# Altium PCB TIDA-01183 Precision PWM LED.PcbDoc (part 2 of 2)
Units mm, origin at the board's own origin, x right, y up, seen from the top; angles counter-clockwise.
Board outline 88 x 70 mm, 2 copper layers (Top Layer, Bottom Layer), stack 1.575 mm thick; 108 components, 41 nets, 240 pads, 138 vias.
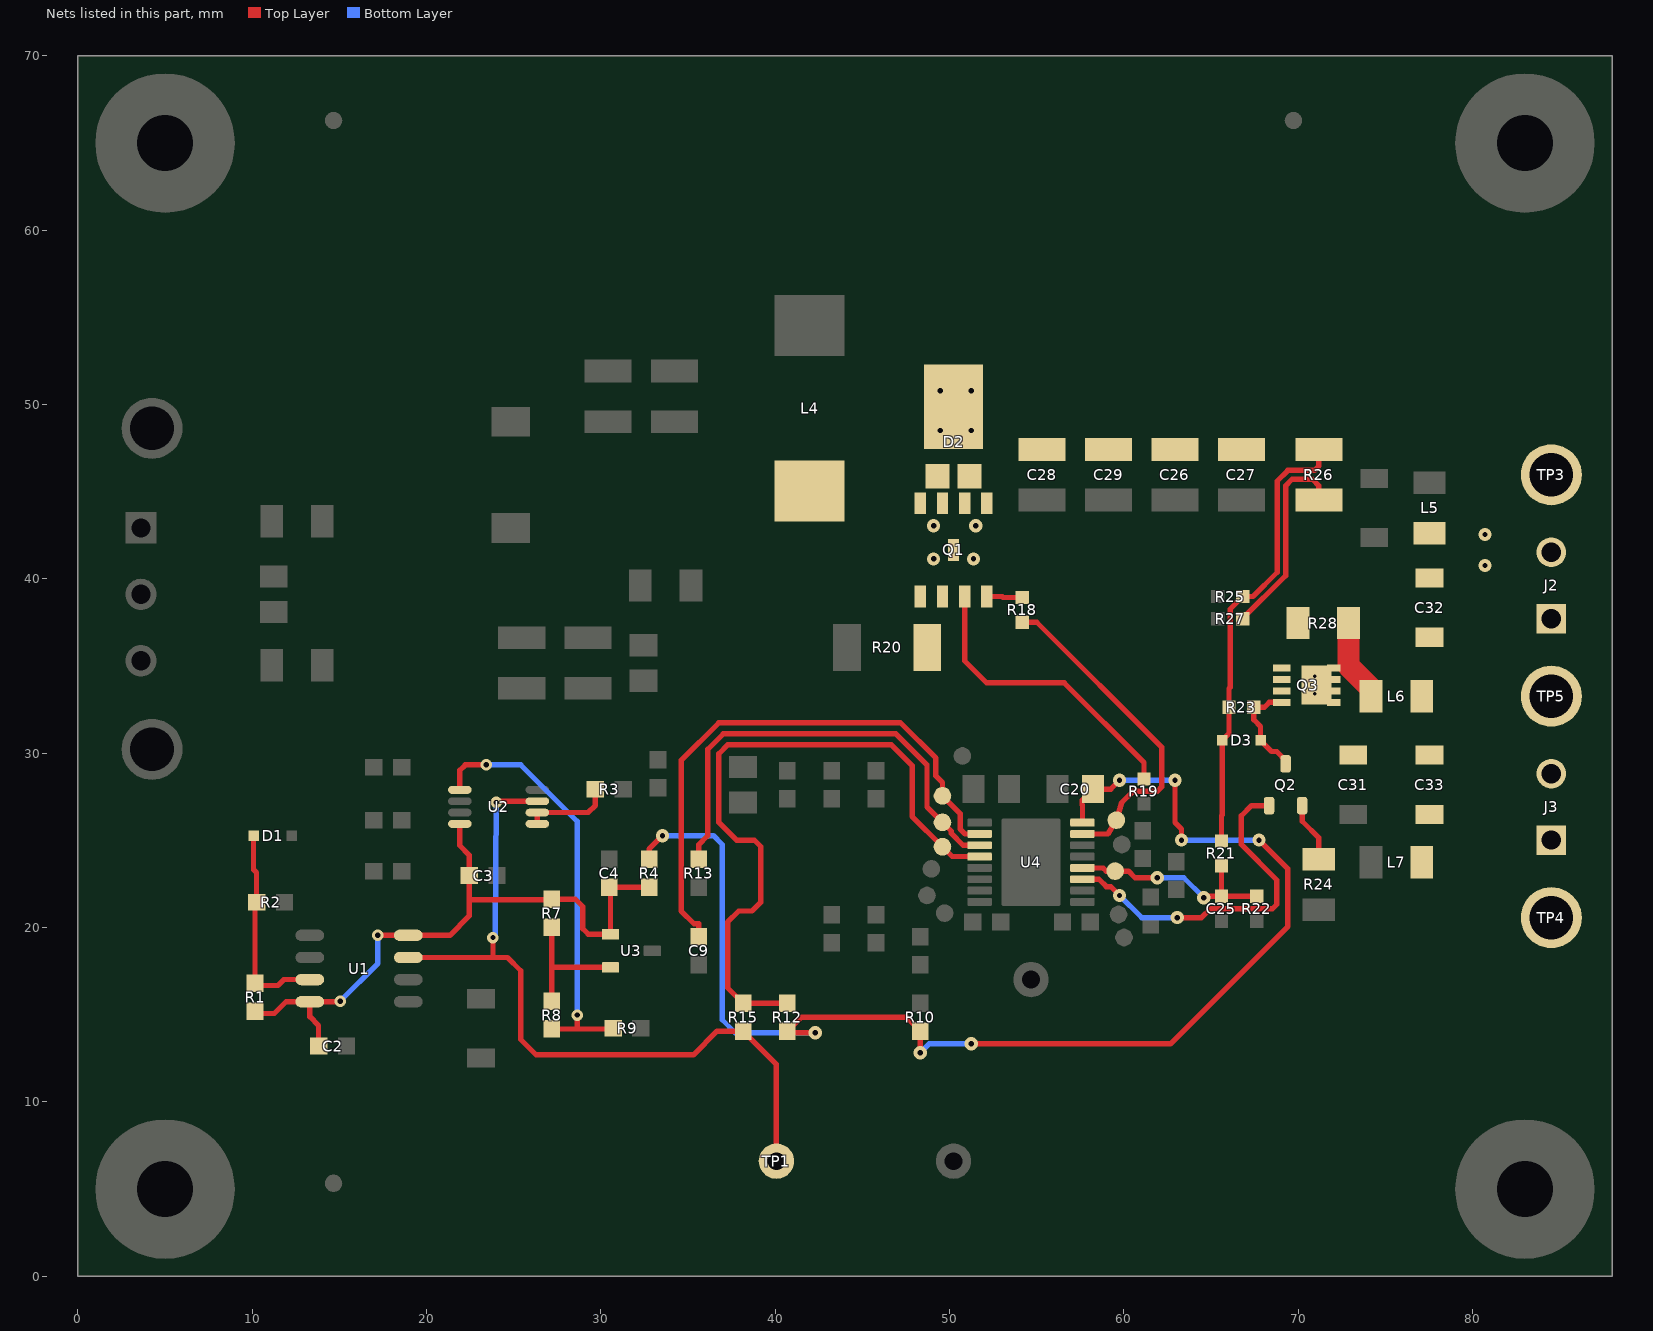
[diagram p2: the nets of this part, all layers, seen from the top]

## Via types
v1: diameter 0.762, hole 0.305, Top Layer to Bottom Layer, tented both sides, 66 vias
v2: diameter 0.66, hole 0.305, Top Layer to Bottom Layer, tented both sides, 49 vias
v3: diameter 0.5, hole 0.2, Top Layer to Bottom Layer, tented both sides, 14 vias
v4: diameter 0.5, hole 0.2, Top Layer to Bottom Layer, 8 vias
v5: diameter 0.762/0.762 (per signal layer), hole 0.305, Top Layer to Bottom Layer, tented both sides, 1 vias

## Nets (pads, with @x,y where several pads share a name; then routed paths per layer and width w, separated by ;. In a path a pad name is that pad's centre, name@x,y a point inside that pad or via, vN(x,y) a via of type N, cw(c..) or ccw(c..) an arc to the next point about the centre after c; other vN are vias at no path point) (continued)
NetC25_1: C25.1 pad.1@59.496,23.241 R21.1 R22.2 U4.12 | length 12.5
  Top Layer w0.305: U4.12@57.62,23.424 58.805,23.424 58.988,23.241 pad.1@59.496,23.241 60.258,23.241 60.639,22.86 v1(61.909,22.86) ; v1(64.576,21.717) 64.652,21.793 C25.1@65.592,21.793 ; R21.1@65.592,23.546 C25.1@65.592,21.793 ; R22.2@67.624,21.793 C25.1@65.592,21.793
  Bottom Layer w0.305: v1(61.909,22.86) 63.433,22.86 v1(64.576,21.717)
NetC26_2: C26.2 C27.2 C28.2 C29.2 D2.3 D3.1 R21.2 R23.2 R25.2 R26.1 | length 26
  Top Layer w0.305: R21.2@65.592,24.968 65.592,26.416 65.635,26.459 D3.1@65.635,30.734 66.024,31.123 R23.2@66.024,32.639 66.024,33.706 66.1,33.782 66.1,38.278 R25.2@66.811,38.989 67.399,38.989 68.792,40.383 68.792,45.618 69.402,46.228 70.926,46.228 71.18,46.482 R26.1@71.18,47.424
  other v1: 49.463,48.514 51.241,48.514 49.463,50.8 51.241,50.8
NetC31_1: C31.1 L6.1 Q3.5 Q3.6 Q3.7 Q3.8 Q3.9 R28.1 | length 4.7
  Top Layer w1.27: R28.1@72.884,37.465 72.884,34.999 74.175,33.708 L6.1@74.175,33.274
  other v4: 70.945,33.401 70.945,34.417
NetC32_1: C32.1 J2.1 L5.2 TP3.1
  other v1: 80.705,40.767 80.705,42.545
NetC32_2: C32.2 C33.1 J2.2 J3.2 L6.2 TP5.1
NetC33_2: C33.2 J3.1 L7.2 TP4.1
NetD1_2: D1.2 R1.1 R2.2 U1.7 | length 11.9
  Top Layer w0.305: D1.2@10.076,25.273 10.076,23.325 10.249,23.152 R2.2@10.249,21.463 10.16,21.374 R1.1@10.16,16.802 ; R1.1@10.16,16.675 11.468,16.675 11.811,17.018 U1.7@13.304,17.018
NetD2_1: D2.1 D2.2 L4.2 Q1.5 Q1.6 Q1.7 Q1.8 Q1.9
  other v1: 49.082,41.148 51.368,41.148 49.082,43.053 51.495,43.053
NetD3_2: D3.2 Q2.3 Q3.4 R23.1 | length 5.9
  Top Layer w0.305: Q3.4@69.053,32.918 68.335,32.918 68.056,32.639 R23.1@67.446,32.639 67.446,31.928 67.835,31.539 D3.2@67.835,30.734 68.47,30.099 68.767,30.099 69.275,29.591 Q2.3@69.275,29.394
NetQ1_1: Q1.1 Q1.2 Q1.3 R19.2 R20.2 | length 17.3
  Top Layer w0.305: Q1.3@50.86,38.989 50.86,35.306 52.13,34.036 56.575,34.036 61.147,29.464 R19.2@61.147,28.524
NetQ1_4: Q1.4 R18.2 | length 2.1
  Top Layer w0.305: Q1.4@52.13,38.989 53.019,38.989 53.07,38.938 R18.2@54.162,38.938
NetQ2_1: Q2.1 U4.11 | length 20.1
  Top Layer w0.305: U4.11@57.62,22.774 58.566,22.774 58.988,22.352 59.242,22.352 v1(59.75,21.844) ; v1(63.052,20.574) 64.449,20.574 64.957,21.082 68.513,21.082 68.767,21.336 68.767,22.733 66.735,24.765 66.735,26.416 67.313,26.994 Q2.1@68.325,26.994
  Bottom Layer w0.305: v1(59.75,21.844) 61.02,20.574 v1(63.052,20.574)
NetQ2_2: Q2.2 R24.2 | length 3.5
  Top Layer w0.305: Q2.2@70.225,26.994 70.225,26.101 71.18,25.146 R24.2@71.18,23.929
NetQ3_1: Q3.1 Q3.2 Q3.3 R26.2 R27.2 R28.2 | length 11.7
  Top Layer w0.305: R27.2@66.811,37.719 69.275,40.183 69.275,45.339 69.656,45.72 70.799,45.72 71.18,45.339 R26.2@71.18,44.524
NetR3_1: R3.1 U2.1 U2.2 | length 5.1
  Top Layer w0.305: U2.1@26.355,25.949 U2.2@26.355,26.599 29.266,26.599 29.68,27.013 R3.1@29.68,27.94
NetR7_1: R7.1 R8.2 U3.2 | length 7.6
  Top Layer w0.305: R8.2@27.178,15.786 27.178,17.78 ; R7.1@27.178,20.028 27.178,17.78 ; U3.2@30.55,17.719 27.239,17.719 27.178,17.78
NetR8_1: R8.1 R9.2 U2.5 | length 24.7
  Top Layer w0.305: U2.5@21.905,27.899 21.905,29.017 22.225,29.337 v2(23.428,29.337) ; R8.1@27.178,14.186 30.658,14.186 R9.2@30.696,14.224 ; 28.635,14.253 v2(28.635,14.986)
  Bottom Layer w0.305: v2(23.428,29.337) 25.4,29.337 28.635,26.102 v2(28.635,14.986)
NetR18_1: pad.1@59.563,26.162 R18.1 U4.15 | length 19.4
  Top Layer w0.305: R18.1@54.162,37.516 55,37.516 62.163,30.353 62.163,28.067 61.909,27.813 60.512,27.813 59.877,27.178 pad.1@59.563,26.162 59.089,25.374 U4.15@57.62,25.374
PREC_PWM: R15.1 TP1.1 U1.3 U2.3 | length 44
  Top Layer w0.305: U1.3@18.954,18.288 23.749,18.288 ; v2(23.809,19.431) 23.809,18.348 23.749,18.288 ; v2(24.003,27.178) 24.074,27.249 U2.3@26.355,27.249 ; TP1.1@40.065,6.604 40.065,12.154 R15.1@38.16,14.059 36.665,14.059 35.306,12.7 26.289,12.7 25.4,13.589 25.4,17.526 24.638,18.288 23.749,18.288
  Bottom Layer w0.305: v2(23.809,19.431) 23.936,19.558 v2(24.003,27.178)
PWM: pad.1@49.59,24.638 R12.2 R15.2 U4.4 | length 39.6
  Top Layer w0.305: R12.2@40.7,15.659 R15.2@38.16,15.659 37.271,16.548 37.271,20.32 37.906,20.955 38.668,20.955 39.176,21.463 39.176,24.638 38.795,25.019 37.779,25.019 36.763,26.035 36.763,29.972 37.271,30.48 46.669,30.48 47.85,29.299 47.85,26.378 pad.1@49.59,24.638 50.154,24.074 U4.4@51.72,24.074
SHUTDOWN: C9.1 pad.1@49.59,27.559 U4.2 | length 33
  Top Layer w0.305: C9.1@35.62,19.38 C9.1@35.62,19.469 35.62,20.219 35.34,20.219 34.604,20.955 34.604,29.591 36.763,31.75 47.177,31.75 49.209,29.718 49.209,28.702 49.59,28.321 pad.1@49.59,27.559 50.606,26.543 50.606,25.654 50.886,25.374 U4.2@51.72,25.374
SYNC: pad.1@49.59,26.035 R13.2 U4.3 | length 26.6
  Top Layer w0.305: R13.2@35.62,23.914 35.62,24.765 36.128,25.273 36.128,30.226 37.017,31.115 46.923,31.115 48.701,29.337 48.701,26.924 pad.1@49.59,26.035 50.098,25.527 50.098,25.4 50.774,24.724 U4.3@51.72,24.724
V5V: C2.1 C3.2 C4.1 R1.2 R4.1 R7.2 U1.4 U1.8 U2.8 U3.1 | length 38.5
  Top Layer w0.305: R1.2@10.16,15.075 11.265,15.075 11.938,15.748 U1.8@13.304,15.748 ; C2.1@13.805,13.208 13.805,14.389 13.304,14.89 U1.8@13.304,15.748 ; v2(15.046,15.781) 15.013,15.748 U1.8@13.304,15.748 ; v2(17.205,19.558) U1.4@18.954,19.558 21.336,19.558 22.441,20.663 22.441,21.59 ; U2.8@21.905,25.949 21.905,24.704 22.441,24.168 C3.2@22.441,22.987 22.441,21.59 ; R4.1@32.766,22.314 C4.1@30.48,22.314 30.55,22.244 U3.1@30.55,19.619 29.276,19.619 28.956,19.939 28.956,21.209 28.537,21.628 R7.2@27.178,21.628 27.14,21.59 22.441,21.59
  Bottom Layer w0.305: v2(15.046,15.781) 17.205,17.94 v2(17.205,19.558)
VCC: C20.1 R4.2 R10.2 R12.1 U4.16 | length 77
  Top Layer w0.305: R4.2@32.766,23.914 32.766,24.511 v1(33.528,25.273) ; v1(42.291,13.97) 40.789,13.97 R12.1@40.7,14.059 41.5,14.859 47.52,14.859 R10.2@48.32,14.059 v1(48.32,12.827) ; v1(51.241,13.335) 62.671,13.335 69.402,20.066 69.402,23.368 v1(67.751,25.019) ; U4.16@57.62,26.024 57.62,27.022 57.591,27.051 57.591,27.305 C20.1@58.226,27.94 59.242,27.94 v1(59.75,28.448) ; v1(62.925,28.448) 62.925,26.035 63.306,25.654 v1(63.306,25.019)
  Bottom Layer w0.305: v1(33.528,25.273) 36.449,25.273 36.957,24.765 36.957,14.713 37.7,13.97 v1(42.291,13.97) ; v1(48.32,12.827) 48.828,13.335 v1(51.241,13.335) ; v1(59.75,28.448) v1(62.925,28.448) ; v1(63.306,25.019) v1(67.751,25.019)
pads on no net: FID1.1 FID2.1 FID3.1 H1.0 H2.1 H3.0 H4.1 H5.1 H6.0 H7.0 H8.1 U4.17@54.67,23.749

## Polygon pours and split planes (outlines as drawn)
NetC31_1 on Top Layer "Top Layer-No Net 12" (solid, remove dead copper, pour order 22): 70.164,35.56 73.839,35.56 74.93,34.469 74.93,29.023 74.736,28.829 71.942,28.829 70.164,30.607
NetC33_2 on Top Layer "Top Layer-No Net 11" (solid, remove dead copper, pour order 21): 85.15,18.415 86.801,20.066 86.801,24.384 85.912,25.273 85.912,27.559 76.387,27.559 76.387,22.733 80.705,18.415
NetC32_2 on Top Layer "Top Layer-No Net 10" (solid, remove dead copper, pour order 17): 86.42,38.608 86.42,40.651 86.42,42.672 84.737,43.053 83.245,42.672 82.102,38.608 77.403,38.608 76.387,37.592 76.387,27.94 84.737,27.94 85.531,28.575 85.531,29.464 86.42,30.353 86.42,37.719
NetC32_1 on Top Layer "Top Layer-No Net 6" (solid, remove dead copper, pour order 18): 78.546,43.434 83.245,48.133 85.785,48.133 86.674,47.244 86.674,40.513 85.277,39.116 76.387,39.116 76.387,43.434
NetQ3_1 on Top Layer "Top Layer-No Net" (solid, remove dead copper, pour order 15): 72.577,45.212 72.577,40.259 72.577,38.989 71.688,38.1 71.688,37.211 69.656,35.179 69.656,33.401 68.132,33.401 67.497,34.036 67.497,37.592 69.783,39.878 69.783,45.212
NetC26_2 on Top Layer "Top Layer-No Net 1" (solid, remove dead copper, pour order 23): 72.748,46.863 72.748,49.486 70.672,51.562 56.448,51.562 55.94,52.07 55.559,52.451 48.447,52.451 48.447,47.498 52.511,47.498 53.146,46.863
NetC18_1 on Top Layer "Top Layer-No Net 3" (solid, remove dead copper, pour order 24): 23.555,46.101 23.555,51.308 31.429,59.182 56.067,59.182 72.577,59.182 78.546,53.213 78.546,44.704 73.339,44.704 73.339,50.165 71.18,52.324 56.702,52.324 56.067,52.959 55.94,53.086 45.78,53.086 43.24,50.546 29.524,50.546 28.635,50.546 28.254,50.165 27.619,49.53 27.619,48.387 27.619,47.371 26.349,46.101
NetD2_1 on Top Layer "Top Layer-No Net 4" (solid, remove dead copper, pour order 25): 40.065,40.513 52.925,40.513 52.925,45.814 52.13,46.609 40.065,46.609
NetQ1_1 on Top Layer "Top Layer-No Net 5" (solid, remove dead copper, pour order 26): 46.796,39.878 49.653,39.878 51.431,39.878 51.431,34.671 46.796,34.671
NetC10_1 on Top Layer "Top Layer-No Net 2" (solid, remove dead copper, pour order 16): 1.838,50.546 5.775,50.546 11.998,44.323 11.998,39.497 7.934,39.497 6.156,41.275 1.838,41.275
NetC10_2 on Top Layer "Top Layer-No Net 8" (solid, remove dead copper, pour order 19): 11.998,38.735 7.553,38.735 5.648,40.64 1.838,40.64 1.838,28.194 6.796,28.194 11.998,33.396
NetC12_1 on Top Layer "Top Layer-No Net 9" (solid, remove dead copper, pour order 20): 33.334,35.433 23.682,35.433 12.954,38.862 12.954,40.259 12.954,44.831 23.682,43.942 29.651,43.942 33.334,40.259
GND on Top Layer "GND_L01_P036" (solid, remove dead copper, pour order 36): 8.128,61.087 8.128,10.414 79.308,10.414 79.435,10.541 79.435,61.214 79.308,61.087 8.128,61.087
GND on Bottom Layer "GND_L02_P034" (solid, remove dead copper, pour order 34): 8.128,61.214 8.128,10.414 79.435,10.414 79.435,61.214 8.128,61.214
NetC32_1 on Bottom Layer "NETC32_1_L02_P030" (solid, remove dead copper, pour order 30): 79.943,43.18 79.943,39.624 79.943,39.497 83.245,36.195 86.293,36.195 86.293,39.243 85.277,40.259 82.229,40.259 82.229,43.434 81.848,43.815 81.594,43.815 80.324,43.815 80.197,43.688

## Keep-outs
Keep-Out Layer:
  text ".Layer_Name" at 0.686,-25.616 h1.52

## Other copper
Top Layer:
  text ".Layer_Name" at 0.686,-25.616 h1.52
Bottom Layer:
  text ".Layer_Name" at 0.686,-25.616 h1.52

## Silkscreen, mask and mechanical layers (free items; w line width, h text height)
Top Overlay:
  lines w0.635: 8.128,10.414 79.435,10.414 79.435,61.214 8.128,61.214 8.128,10.414
  text "TIDA-01183 Precision PWM LED Driver" at 23.174,66.167 h1.27
  text "INPUT" at 1.016,58.547 h0.76
  text "MAX" at 81.467,58.039 h0.76
  text "VOLTAGE" at 0.889,57.023 h0.76
  text "OUTPUT" at 80.451,56.769 h0.76
  text "RANGE" at 1.27,55.626 h0.76
  text "RANGE" at 80.959,55.499 h0.76
  text "LED+toGND" at 80.137,54.102 h0.76
  text "4.5-18VDC" at 0.381,53.975 h0.76
  text "65V" at 81.467,52.832 h0.76
  text "Precision PWM LED Driver" at 58.607,14.478 h1.78
  text ".PCB_Rev" at 69.723,12.954 h1.02
  text ".PRJ_Number" at 58.547,12.827 h1.02
  text "PWM" at 38.16,5.334 h0.76 r90
  text "IMON" at 48.32,5.334 h0.76 r90
  text ".Layer_Name" at 0.686,-25.616 h1.52
Bottom Overlay:
  text ".Layer_Name" at 0.686,-25.616 h1.52
Top Paste:
  text ".Layer_Name" at 0.686,-25.616 h1.52
Bottom Paste:
  text ".Layer_Name" at 0.686,-25.616 h1.52
Top Solder:
  text ".Layer_Name" at 0.686,-25.616 h1.52
  text ".Layer_Name" at 0.686,-25.616 h1.52
Bottom Solder:
  rectangle: 53.429,22.116 55.842,25.672
  text ".Layer_Name" at 0.686,-25.616 h1.52
Drill Guide:
  text ".Layer_Name" at 0.686,-25.616 h1.52
M1 Board Outline:
  the board outline again, w0.254
  text ".Layer_Name" at 0.686,-25.616 h1.52
M2 Board Dimensions:
  text ".Layer_Name" at 0.686,-25.616 h1.52
M3 3D STEP Top:
  text ".Layer_Name" at 0.686,-25.616 h1.52
M4 3D STEP Bottom:
  text ".Layer_Name" at 0.686,-25.616 h1.52
M5 Assembly Top:
  lines w0.254: -21.387,-27.436 146.253,-27.436 ; -21.387,-22.272 146.304,-22.272 ; -21.387,-17.107 -21.387,-32.601 80.34,-32.601 146.304,-32.601 146.304,-17.107 -21.374,-17.107 -21.374,-32.601 18.644,-32.601 ; 41.224,-32.601 41.224,-17.107 ; 73.406,-22.272 73.406,-17.107 ; 94.742,-22.272 94.742,-17.107 ; 110.541,-32.766 110.541,-27.614
  text "COMPONENTS MARKED 'DNP' SHOULD NOT BE POPULATED." at 15.329,-11.9 h1.52
  text "ASSEMBLY VARIANT:" at 15.316,-14.834 h1.52
  text ".VariantName" at 41.631,-14.834 h1.52
  text "PCB VIEWED FROM TOP SIDE" at -19.774,-20.464 h1.52
  text "BOARD #:" at 43.129,-20.464 h1.52
  text ".PRJ_Number" at 56.985,-20.464 h1.52
  text "REV:" at 78.435,-20.464 h1.52
  text ".PCB_Rev" at 85.839,-20.464 h1.52
  text "SVN REV:" at 99.72,-20.464 h1.52
  text ".VersionControl_RevNumber" at 112.573,-20.464 h1.52
  text "TID #:" at 43.129,-25.629 h1.52
  text ".TID" at 56.985,-25.629 h1.52
  text "PLOT NAME =" at -19.774,-30.844 h1.52
  text "GENERATED    :" at 43.18,-30.844 h1.52
  text ".Print_Date" at 65.265,-30.844 h1.52
  text ".Print_Time" at 83.782,-30.844 h1.52
  text "TEXAS INSTRUMENTS" at 115.9,-30.844 h1.52
M6 Assembly Bottom:
  lines w0.254: -21.399,-22.284 146.291,-22.284 ; -21.349,-27.449 146.291,-27.449 ; 14.364,-32.779 14.364,-27.627 ; 30.163,-22.284 30.163,-17.12 ; 51.499,-22.284 51.499,-17.12 ; 83.68,-32.614 83.68,-17.12 ; 106.261,-32.614 146.279,-32.614 146.279,-17.12 -21.399,-17.12 -21.399,-32.614 44.564,-32.614 146.291,-32.614 146.291,-17.12
  text "COMPONENTS MARKED 'DNP' SHOULD NOT BE POPULATED." at 141.021,-11.887 h1.52
  text ".VariantName" at 114.503,-14.834 h1.52
  text "ASSEMBLY VARIANT:" at 140.894,-14.834 h1.52
  text ".VersionControl_RevNumber" at 12.332,-20.477 h1.52
  text "SVN REV:" at 25.184,-20.477 h1.52
  text ".PCB_Rev" at 39.065,-20.477 h1.52
  text "REV:" at 46.469,-20.477 h1.52
  text ".PRJ_Number" at 67.92,-20.477 h1.52
  text "BOARD #:" at 81.775,-20.477 h1.52
  text "PCB VIEWED FROM BOTTOM SIDE" at 144.678,-20.477 h1.52
  text ".TID" at 67.92,-25.641 h1.52
  text "TID #:" at 81.775,-25.641 h1.52
  text "TEXAS INSTRUMENTS" at 9.004,-30.857 h1.52
  text ".Print_Time" at 41.123,-30.857 h1.52
  text ".Print_Date" at 59.639,-30.857 h1.52
  text "GENERATED    :" at 81.725,-30.857 h1.52
  text ".plot_File_Name" at 124.219,-30.857 h1.52
  text "PLOT NAME =" at 144.678,-30.857 h1.52
M9 Title Sheet:
  drawing of 57 lines, arcs and shapes, not listed
  text "1" at 4.822,200.317 h1.78
  text "2" at 68.212,200.317 h1.78
  text "3" at 131.441,200.317 h1.78
  text "4" at 195.11,200.317 h1.78
  text "5" at 258.585,200.317 h1.78
  text "6" at 322.212,200.317 h1.78
  text "A" at -24.549,171.285 h1.78
  text "A" at 351.371,171.285 h1.78
  text "B" at -24.549,110.833 h1.78
  text "B" at 351.371,110.833 h1.78
  text "C" at -24.549,50.508 h1.78
  text "C" at 351.371,50.508 h1.78
  text "PROJECT TITLE:" at 274.155,3.239 h1.14
  text ".PRJ_Title" at 275.425,-0.148 h1.78
  text "DESIGNED FOR:" at 274.155,-4.407 h1.14
  text ".PRJ_Customer" at 275.425,-7.963 h1.78
  text "D" at -24.549,-9.69 h1.78
  text "D" at 351.371,-9.69 h1.78
  text "FILE NAME:" at 274.155,-12.027 h1.14
  text ".PCB_File_Name_No_Path" at 275.425,-15.075 h1.78
  text "Texas Instruments (TI) and/or its licensors do not warrant the accuracy or completeness of this specification" at 147.93,-19.186 h1.14
  text "ENGINEER:" at 274.155,-19.393 h1.14
  text "LAYOUT BY:" at 312.382,-19.393 h1.14
  text "or any information contained therein. TI and/or its licensors do not warrant that this design will meet" at 146.787,-22.047 h1.14
  text ".PRJ_Engineer" at 275.425,-23.33 h1.78
  text ".PCB_Layout" at 313.665,-23.33 h1.78
  text "the specifications, will be suitable for your application or fit for any particular purpose, or will operate in" at 146.787,-24.909 h1.14
  text ".Layer_Name" at 0.686,-25.616 h1.52
  text "ALTIUM DESIGNER VERSION:" at 312.382,-27.267 h1.14
  text "an implementation. TI and/or its licensors do not warrant that the design is production worthy. You should" at 146.787,-27.771 h1.14
  text "completely validate and test your design implementation to confirm the system functionality for your application." at 147.93,-30.632 h1.14
  text ".print_Scale" at 275.425,-30.653 h1.78
  text ".Application_BuildNumber" at 313.665,-30.653 h1.78
  text "1" at 4.822,-35.903 h1.78
  text "2" at 68.212,-35.903 h1.78
  text "3" at 131.441,-35.903 h1.78
  text "4" at 195.11,-35.903 h1.78
  text "5" at 258.585,-35.903 h1.78
  text "6" at 322.212,-35.903 h1.78
M10 Fab Notes:
  drawing of 185 lines, arcs and shapes, not listed
  text "DESIGN INFORMATION" at 300.508,146.304 h1.52
  text "MIN. TRACK WIDTH:" at 284.136,141.732 h1.52
  text "10" at 311.277,141.732 h1.52
  text "MIL" at 315.911,141.732 h1.52
  text "7" at 312.801,138.557 h1.52
  text "MIN. CLEARANCE:" at 284.136,138.379 h1.52
  text "MIL" at 315.911,138.379 h1.52
  text "MIN. VIA PAD SIZE:" at 284.136,135.026 h1.52
  text "26" at 311.219,135.026 h1.52
  text "MIL" at 315.911,135.026 h1.52
  text "0.05mm (2MIL)" at 301.789,131.427 h1.52
  text "MINIMUM ANNULAR RING" at 275.774,131.318 h1.52
  text "EXTERNAL" at 319.772,131.318 h1.52
  text "PER" at 280.854,128.321 h1.52
  text "IPC-D-275 CLASS 2 LEVEL C" at 286.442,128.321 h1.52
  text "MIL, HOLES" at 324.243,125.469 h1.52
  text "+/-" at 314.274,125.451 h1.52
  text "+/-" at 335.966,125.451 h1.52
  text "REGISTRATION TOLERANCES:" at 275.774,125.324 h1.52
  text "METAL" at 306.248,125.324 h1.52
  text "5" at 320.883,125.324 h1.52
  text "3" at 342.042,125.324 h1.52
  text "MIL" at 344.994,125.324 h1.52
  text "MATERIAL:" at 273.874,120.003 h1.52
  text "FR-4 High Tg" at 298.93,116.439 h1.52
  text "FR-408" at 284.568,116.221 h1.52
  text "X" at 295.033,116.221 h1.52
  text "OTHER" at 322.363,116.221 h1.52
  text "62 MIL (1.6mm) +/-10%" at 292.698,112.088 h1.52
  text "THICKNESS:" at 275.774,111.979 h1.52
  text "X" at 289.443,111.979 h1.52
  text "OTHER" at 325.335,111.979 h1.52
  text "TOLERANCE:" at 275.774,107.966 h1.52
  text "X" at 297.092,107.966 h1.52
  text "ANSI IPC-6012 TYPE 3 CLASS 2" at 301.84,107.966 h1.52
  text "OTHER +/-" at 301.84,104.004 h1.52
  text "BOW & TWIST:" at 275.774,100.016 h1.52
  text "X" at 297.092,100.016 h1.52
  text "ANSI IPC-6012 TYPE 3 CLASS 2" at 301.84,100.016 h1.52
  text "OTHER +/-" at 301.84,95.99 h1.52
  text "DRILLING:" at 273.874,92.472 h1.52
  text "REFERENCE:" at 275.774,89.5 h1.52
  text "X" at 292.239,89.5 h1.52
  text "AS SHOWN" at 296.988,89.5 h1.52
  text "X" at 315.124,89.5 h1.52
  text "NC_DRILL FILES" at 318.604,89.5 h1.52
  text "PTH MIN COPPER THICKNESS:" at 275.774,85.487 h1.52
  text "X" at 310.069,85.487 h1.52
  text "1MIL" at 313.549,85.487 h1.52
  text "OTHER" at 326.173,85.487 h1.52
  text "BOARD FINISH:" at 273.874,81.449 h1.52
  text "SILKSCREEN:" at 277.817,78.451 h1.52
  text "X" at 301.916,78.451 h1.52
  text "TOP" at 305.116,78.451 h1.52
  text "BOTTOM" at 318.096,78.451 h1.52
  text "SILKSCREEN COLOR:" at 277.817,74.21 h1.52
  text "X" at 301.89,74.21 h1.52
  text "WHITE" at 305.116,74.21 h1.52
  text "OTHER" at 318.096,74.21 h1.52
  text "SOLDER RESIST COLOR:" at 277.817,69.892 h1.52
  text "X" at 292.238,65.848 h1.52
  text "GREEN" at 295.464,65.848 h1.52
  text "BLUE" at 310.476,65.848 h1.52
  text "OTHER" at 324.141,65.848 h1.52
  text "IMMERSION GOLD (ENIG)" at 300.824,61.06 h1.52
  text "ENEPIG" at 334.797,60.976 h1.52
  text "SURFACE FINISH:" at 273.874,60.951 h1.52
  text "IMM. TIN/SILVER OR EQUIV" at 282.245,56.963 h1.52
  text "OTHER" at 318.604,56.963 h1.52
  text "X" at 278.13,56.896 h1.52
  text "ARRAY/PANEL:" at 273.874,52.416 h1.52
  text "X" at 295.91,52.324 h1.52
  text "CUT AND TRIM PER MECH LAYER 1" at 300.824,52.308 h1.52
  text "N.C. ROUTE" at 300.824,48.454 h1.52
  text "V. SCORE" at 322.82,48.454 h1.52
  text "CERTIFICATION:" at 273.874,44.974 h1.52
  text "MATERIALS AND WORKMANSHIP FOR ALL PCBS" at 292.289,44.974 h1.52
  text "TO MEET OR EXCEED THE REQUIREMENTS OF:" at 292.289,42.485 h1.52
  text "X" at 282.803,39.018 h1.52
  text "ANSI IPC-A-600F CLASS ->" at 286.333,39.018 h1.52
  text "X" at 327.965,39.018 h1.52
  text "2" at 330.986,39.018 h1.52
  text "1" at 322.985,38.98 h1.52
  text "3" at 339.978,38.98 h1.52
  text "X" at 282.855,34.967 h1.52
  text "UL 94V-0" at 286.333,34.967 h1.52
  text "X" at 303.48,34.967 h1.52
  text "RoHS" at 306.958,34.967 h1.52
  text "OTHER" at 323.326,34.967 h1.52
  text "ADDITIONAL REQUIREMENTS:" at 273.874,31.385 h1.52
  text "MICROSECTION:" at 275.774,28.464 h1.52
  text "YES" at 298.779,28.464 h1.52
  text "REQUIRED" at 320.661,24.498 h1.52
  text "BARE BOARD ELEC. TEST:" at 275.774,24.426 h1.52
  text "NONE" at 308.939,24.426 h1.52
  text "PER ORDER" at 335.698,24.426 h1.52
  text "X" at 305.689,24.384 h1.52
  text "MANUFACTURER'S UL:" at 275.774,20.438 h1.52
  text "RAIL" at 305.383,20.329 h1.52
  text "METAL" at 317.875,20.329 h1.52
  text "X" at 327.406,20.32 h1.52
  text "SILK" at 330.872,20.329 h1.52
  text ".Layer_Name" at 0.686,-25.616 h1.52
M11 Gerber Information:
  lines w0.254: -21.387,-27.436 146.253,-27.436 ; -21.387,-22.272 146.304,-22.272 ; -21.387,-17.107 -21.387,-32.601 80.34,-32.601 146.304,-32.601 146.304,-17.107 -21.374,-17.107 -21.374,-32.601 18.644,-32.601 ; 41.224,-32.601 41.224,-17.107 ; 73.406,-22.272 73.406,-17.107 ; 94.742,-22.272 94.742,-17.107 ; 110.541,-32.766 110.541,-27.614
  text "ALL ARTWORK VIEWED FROM TOP SIDE" at -19.774,-20.464 h1.52
  text "BOARD #:" at 43.129,-20.464 h1.52
  text ".PRJ_Number" at 56.985,-20.464 h1.52
  text "REV:" at 78.435,-20.464 h1.52
  text ".PCB_Rev" at 85.839,-20.464 h1.52
  text "SVN REV:" at 99.72,-20.464 h1.52
  text ".VersionControl_RevNumber" at 112.573,-20.464 h1.52
  text "LAYER NAME =" at -19.774,-25.616 h1.52
  text "TID #:" at 43.129,-25.629 h1.52
  text ".TID" at 56.985,-25.629 h1.52
  text "PLOT NAME =" at -19.774,-30.844 h1.52
  text ".plot_File_Name" at 0.686,-30.844 h1.52
  text "GENERATED    :" at 43.18,-30.844 h1.52
  text ".Print_Date" at 65.265,-30.844 h1.52
  text ".Print_Time" at 83.782,-30.844 h1.52
  text "TEXAS INSTRUMENTS" at 115.9,-30.844 h1.52
M12 Stackup:
  drawing of 305 lines, arcs and shapes, not listed
  text "Layer" at 172.877,188.341 h1.52
  text "Name" at 183.289,188.341 h1.52
  text "Material" at 205.127,188.341 h1.52
  text "Thickness" at 226.965,188.341 h1.52
  text "Constant" at 243.471,188.341 h1.52
  text "Board Layer Stack" at 257.945,188.341 h1.52
  text "Board Layer Stack" at 286.385,188.341 h1.52
  text "Board Layer Stack" at 314.825,188.341 h1.52
  text "1" at 172.877,185.293 h1.52
  text "Top Overlay" at 183.289,185.293 h1.52
  text "2" at 172.877,182.245 h1.52
  text "Top Solder" at 183.289,182.245 h1.52
  text "Solder Resist" at 205.127,182.245 h1.52
  text "0.40mil" at 226.965,182.245 h1.52
  text "3.5" at 243.471,182.245 h1.52
  text "3" at 172.877,179.197 h1.52
  text "Top Layer" at 183.289,179.197 h1.52
  text "Copper" at 205.127,179.197 h1.52
  text "1.40mil" at 226.965,179.197 h1.52
  text "4" at 172.877,176.149 h1.52
  text "Dielectric1" at 183.289,176.149 h1.52
  text "FR-4" at 205.127,176.149 h1.52
  text "59.20mil" at 226.965,176.149 h1.52
  text "4.8" at 243.471,176.149 h1.52
  text "5" at 172.877,173.101 h1.52
  text "Bottom Layer" at 183.289,173.101 h1.52
  text "Copper" at 205.127,173.101 h1.52
  text "1.40mil" at 226.965,173.101 h1.52
  text "6" at 172.877,170.053 h1.52
  text "Bottom Solder" at 183.289,170.053 h1.52
  text "Solder Resist" at 205.127,170.053 h1.52
  text "0.40mil" at 226.965,170.053 h1.52
  text "3.5" at 243.471,170.053 h1.52
  text ".Layer_Name" at 0.686,-25.616 h1.52
M13 Component Bodies Top:
  text ".Layer_Name" at 0.686,-25.616 h1.52
M14 Component Bodies Bottom:
  text ".Layer_Name" at 0.686,-25.616 h1.52
M15 Courtyards Top:
  text ".Layer_Name" at 0.686,-25.616 h1.52
M16 Courtyards Bottom:
  text ".Layer_Name" at 0.686,-25.616 h1.52
Drill Drawing:
  circle w0.254: c103.726,41.394 r0.702
  lines w0.254: 103.025,45.253 104.428,45.253 103.726,43.85 103.025,45.253 ; 103.025,47.008 104.428,47.008 104.428,48.411 103.025,48.411 103.025,47.008 ; 103.025,50.165 104.428,50.165 104.428,51.569 103.025,51.569 103.025,50.165 ; 103.025,53.674 103.376,53.674 103.726,53.323 104.077,53.674 104.428,53.674 104.077,54.025 104.428,54.376 104.077,54.376 103.726,54.727 103.376,54.376 103.025,54.376 103.376,54.025 103.025,53.674 ; 103.025,57.884 104.428,57.884 103.726,56.481 103.025,57.884 ; 103.305,47.288 104.147,47.288 104.147,48.13 103.305,48.13 103.305,47.288 ; 103.305,53.814 103.516,53.814 103.726,53.604 103.937,53.814 104.147,53.814 103.937,54.025 104.147,54.235 103.937,54.235 103.726,54.446 103.516,54.235 103.305,54.235 103.516,54.025 103.305,53.814 ; 103.305,57.604 104.147,57.604 103.726,56.762 103.305,57.604
  lines w0.305: 101.752,39.745 183.832,39.745 ; 101.752,58.691 183.832,58.691 ; 110.334,36.587 110.334,61.849 ; 118.767,36.587 118.767,61.849 ; 134.936,36.587 134.936,61.849 ; 141.518,36.587 141.518,61.849 ; 151.047,36.587 151.047,61.849 ; 169.445,36.587 169.445,61.849 ; 101.752,36.587 183.832,36.587 183.832,61.849 101.752,61.849 101.752,36.587
  text "Symbol" at 103.647,59.639 h1.83
  text "Quantity" at 111.281,59.639 h1.83
  text "Finished Hole Size" at 119.714,59.639 h1.83
  text "Plated" at 135.883,59.639 h1.83
  text "Hole Type" at 142.465,59.639 h1.83
  text "Drill Layer Pair" at 151.994,59.639 h1.83
  text "Hole Tolerance" at 170.392,59.639 h1.83
  text "22" at 111.281,56.481 h1.52
  text "0.200mm (7.87mil)" at 119.714,56.481 h1.52
  text "PTH" at 135.883,56.481 h1.52
  text "Round" at 142.465,56.481 h1.52
  text "Top Layer - Bottom Layer" at 151.994,56.481 h1.52
  text "116" at 111.281,53.323 h1.52
  text "0.305mm (12.00mil)" at 119.714,53.323 h1.52
  text "PTH" at 135.883,53.323 h1.52
  text "Round" at 142.465,53.323 h1.52
  text "Top Layer - Bottom Layer" at 151.994,53.323 h1.52
  text "3" at 111.281,50.165 h1.52
  text "1.016mm (40.00mil)" at 119.714,50.165 h1.52
  text "PTH" at 135.883,50.165 h1.52
  text "Round" at 142.465,50.165 h1.52
  text "Top Layer - Bottom Layer" at 151.994,50.165 h1.52
  text "7" at 111.281,47.008 h1.52
  text "1.100mm (43.31mil)" at 119.714,47.008 h1.52
  text "PTH" at 135.883,47.008 h1.52
  text "Round" at 142.465,47.008 h1.52
  text "Top Layer - Bottom Layer" at 151.994,47.008 h1.52
  text "5" at 111.281,43.85 h1.52
  text "2.500mm (98.43mil)" at 119.714,43.85 h1.52
  text "PTH" at 135.883,43.85 h1.52
  text "Round" at 142.465,43.85 h1.52
  text "Top Layer - Bottom Layer" at 151.994,43.85 h1.52
  text "4" at 111.281,40.692 h1.52
  text "3.200mm (125.98mil)" at 119.714,40.692 h1.52
  text "PTH" at 135.883,40.692 h1.52
  text "Round" at 142.465,40.692 h1.52
  text "Top Layer - Bottom Layer" at 151.994,40.692 h1.52
  text "157 Total" at 111.281,37.534 h1.52

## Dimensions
0,0 to 88,0 on M2 Board Dimensions
0,70 to 0,0 on M2 Board Dimensions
